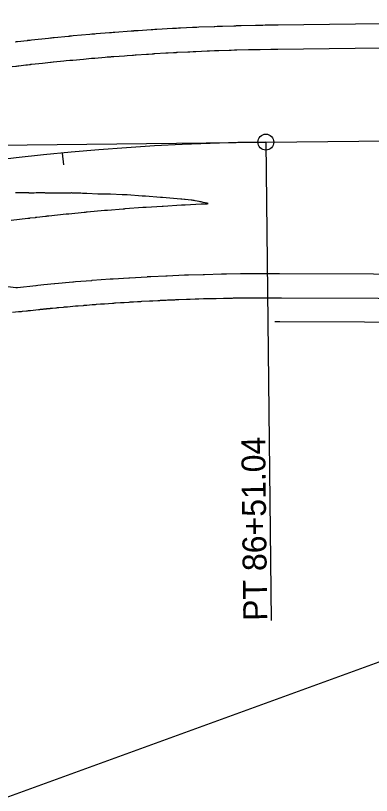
# Model space of a CAD drawing. Extents: x 1710723 to 1713003, y 548603 to 551142.
# Drawn here: x 1711329.1 to 1711418.2, y 549044.7 to 549240.3 of the extents above; entities that cross this region are included whole.
import ezdxf

# ---------------------------------------------------------------- set-up
doc = ezdxf.new("R2010")
doc.units = 0
for name, color, linetype in [('R_Contours', 7, 'Continuous'), ('R_Horz Alg', 7, 'Continuous'), ('R_Horz Alg Annot', 7, 'Continuous'), ('R_No Plot', 7, 'Continuous'), ('R_Striping', 7, 'Continuous')]:
    doc.layers.add(name, color=color, linetype=linetype)

msp = doc.modelspace()

# ---------------------------------------------------------------- linework, layer by layer
at = {"layer": 'R_Contours'}
for points in [[(1711581.85, 549240.26), (1711394.88, 549237.87), (1711394.67, 549237.87), (1711394.45, 549237.87), (1711394.24, 549237.86), (1711394.02, 549237.86), (1711391.64, 549237.82), (1711391.06, 549237.81), (1711390.38, 549237.8), (1711390.3, 549237.8), (1711390.21, 549237.8), (1711390.12, 549237.8), (1711390.03, 549237.79), (1711389.44, 549237.78), (1711389.31, 549237.78), (1711389.28, 549237.78), (1711389.25, 549237.78), (1711389.21, 549237.78), (1711389.18, 549237.78), (1711385.62, 549237.69), (1711385.15, 549237.68), (1711384.36, 549237.66), (1711384.2, 549237.65), (1711384.04, 549237.65), (1711383.88, 549237.64), (1711383.73, 549237.64), (1711380.94, 549237.55), (1711380.45, 549237.53), (1711379.9, 549237.51), (1711379.81, 549237.51), (1711379.73, 549237.51), (1711379.64, 549237.5), (1711379.55, 549237.5), (1711378.99, 549237.48), (1711378.89, 549237.48), (1711378.84, 549237.47), (1711378.79, 549237.47), (1711375.01, 549237.32), (1711374.46, 549237.29), (1711373.91, 549237.27), (1711373.77, 549237.26), (1711373.64, 549237.26), (1711373.5, 549237.25), (1711373.36, 549237.25), (1711370.35, 549237.1), (1711369.91, 549237.08), (1711369.41, 549237.05), (1711369.33, 549237.05), (1711369.25, 549237.04), (1711369.17, 549237.04), (1711369.09, 549237.03), (1711368.56, 549237.01), (1711368.46, 549237), (1711368.42, 549237), (1711368.4, 549237), (1711364.45, 549236.77), (1711363.97, 549236.74), (1711363.48, 549236.71), (1711363.36, 549236.71), (1711363.24, 549236.7), (1711363.12, 549236.69), (1711363, 549236.68), (1711359.78, 549236.47), (1711359.38, 549236.44), (1711358.94, 549236.42), (1711358.86, 549236.41), (1711358.79, 549236.41), (1711358.71, 549236.4), (1711358.63, 549236.39), (1711358.08, 549236.36), (1711358.03, 549236.35), (1711358.01, 549236.35), (1711353.97, 549236.05), (1711353.52, 549236.02), (1711353.08, 549235.98), (1711352.96, 549235.97), (1711352.85, 549235.97), (1711352.74, 549235.96), (1711352.63, 549235.95), (1711349.27, 549235.67), (1711348.89, 549235.64), (1711348.47, 549235.61), (1711348.4, 549235.6), (1711348.33, 549235.59), (1711348.26, 549235.59), (1711348.19, 549235.58), (1711347.69, 549235.54), (1711347.65, 549235.54), (1711347.64, 549235.53), (1711343.5, 549235.16), (1711343.09, 549235.12), (1711342.68, 549235.08), (1711342.58, 549235.07), (1711342.48, 549235.06), (1711342.38, 549235.05), (1711342.28, 549235.04), (1711338.76, 549234.7), (1711338.41, 549234.66), (1711338.02, 549234.62), (1711337.96, 549234.62), (1711337.89, 549234.61), (1711337.83, 549234.6), (1711337.77, 549234.6), (1711337.32, 549234.55), (1711337.28, 549234.55), (1711333.06, 549234.09), (1711332.68, 549234.05), (1711332.31, 549234.01), (1711332.22, 549234), (1711332.12, 549233.99), (1711332.03, 549233.98), (1711331.94, 549233.97), (1711329.56, 549233.7), (1711329.19, 549233.66), (1711329.14, 549233.65), (1711329.09, 549233.64), (1711329.03, 549233.64)], [(1711328.22, 549227.48), (1711329.11, 549227.6), (1711329.31, 549227.62), (1711329.64, 549227.66), (1711329.71, 549227.67), (1711329.77, 549227.68), (1711329.84, 549227.69), (1711329.91, 549227.7), (1711331.66, 549227.9), (1711332.03, 549227.94), (1711332.53, 549228), (1711332.66, 549228.01), (1711332.78, 549228.03), (1711332.91, 549228.04), (1711333.03, 549228.05), (1711335.79, 549228.35), (1711336.43, 549228.42), (1711337.81, 549228.57), (1711337.86, 549228.57), (1711337.91, 549228.58), (1711337.96, 549228.58), (1711338.01, 549228.59), (1711338.45, 549228.63), (1711338.5, 549228.64), (1711338.55, 549228.64), (1711341.18, 549228.9), (1711341.74, 549228.96), (1711342.67, 549229.05), (1711342.85, 549229.07), (1711343.04, 549229.09), (1711343.23, 549229.11), (1711343.41, 549229.12), (1711346.08, 549229.37), (1711346.71, 549229.42), (1711348.06, 549229.55), (1711348.12, 549229.55), (1711348.18, 549229.56), (1711348.23, 549229.56), (1711348.29, 549229.57), (1711348.68, 549229.6), (1711348.78, 549229.61), (1711348.84, 549229.61), (1711348.89, 549229.62), (1711351.5, 549229.83), (1711352.05, 549229.88), (1711352.95, 549229.95), (1711353.13, 549229.97), (1711353.32, 549229.98), (1711353.5, 549230), (1711353.68, 549230.01), (1711356.39, 549230.21), (1711357.01, 549230.26), (1711358.33, 549230.36), (1711358.39, 549230.36), (1711358.46, 549230.37), (1711358.52, 549230.37), (1711358.58, 549230.38), (1711359.02, 549230.41), (1711359.13, 549230.41), (1711359.19, 549230.42), (1711359.25, 549230.42), (1711361.84, 549230.59), (1711362.37, 549230.63), (1711363.25, 549230.69), (1711363.43, 549230.7), (1711363.6, 549230.71), (1711363.78, 549230.72), (1711363.96, 549230.73), (1711366.71, 549230.89), (1711367.32, 549230.92), (1711368.61, 549231), (1711368.68, 549231), (1711368.75, 549231.01), (1711368.82, 549231.01), (1711368.89, 549231.02), (1711369.37, 549231.04), (1711369.49, 549231.05), (1711369.53, 549231.05), (1711369.56, 549231.05), (1711369.59, 549231.05), (1711369.62, 549231.05), (1711372.21, 549231.18), (1711372.72, 549231.21), (1711373.56, 549231.25), (1711373.73, 549231.26), (1711373.9, 549231.26), (1711374.07, 549231.27), (1711374.24, 549231.28), (1711377.07, 549231.4), (1711377.66, 549231.42), (1711378.9, 549231.47), (1711378.98, 549231.48), (1711379.05, 549231.48), (1711379.13, 549231.48), (1711379.21, 549231.48), (1711379.73, 549231.5), (1711379.87, 549231.51), (1711379.9, 549231.51), (1711379.93, 549231.51), (1711379.97, 549231.51), (1711380, 549231.51), (1711382.59, 549231.6), (1711383.07, 549231.61), (1711383.88, 549231.64), (1711384.05, 549231.64), (1711384.21, 549231.65), (1711384.37, 549231.65), (1711384.53, 549231.66), (1711387.45, 549231.73), (1711388.03, 549231.75), (1711389.19, 549231.78), (1711389.28, 549231.78), (1711389.36, 549231.78), (1711389.45, 549231.78), (1711389.53, 549231.78), (1711390.11, 549231.79), (1711390.25, 549231.8), (1711390.28, 549231.8), (1711390.32, 549231.8), (1711390.35, 549231.8), (1711390.38, 549231.8), (1711393.01, 549231.84), (1711393.47, 549231.85), (1711394.22, 549231.86), (1711394.37, 549231.86), (1711394.52, 549231.87), (1711394.67, 549231.87), (1711394.82, 549231.87), (1711581.92, 549234.26)], [(1711327.96, 549188.93), (1711332.12, 549189.45), (1711332.17, 549189.45), (1711332.23, 549189.46), (1711332.59, 549189.5), (1711332.66, 549189.51), (1711332.72, 549189.52), (1711333.95, 549189.66), (1711334.06, 549189.67), (1711334.16, 549189.69), (1711334.26, 549189.7), (1711334.36, 549189.71), (1711336.58, 549189.96), (1711336.78, 549189.98), (1711336.98, 549190.01), (1711337.18, 549190.03), (1711337.38, 549190.05), (1711341.75, 549190.52), (1711341.8, 549190.52), (1711341.85, 549190.53), (1711342.26, 549190.57), (1711342.3, 549190.58), (1711342.35, 549190.58), (1711342.39, 549190.58), (1711342.44, 549190.59), (1711346.26, 549190.96), (1711346.44, 549190.98), (1711346.61, 549191), (1711346.79, 549191.02), (1711346.97, 549191.03), (1711351.32, 549191.43), (1711351.38, 549191.43), (1711351.44, 549191.44), (1711351.49, 549191.44), (1711351.55, 549191.45), (1711352.02, 549191.49), (1711352.06, 549191.49), (1711352.1, 549191.49), (1711356.02, 549191.81), (1711356.14, 549191.82), (1711356.26, 549191.83), (1711356.38, 549191.84), (1711356.5, 549191.85), (1711360.95, 549192.18), (1711361.02, 549192.18), (1711361.09, 549192.19), (1711361.16, 549192.19), (1711361.23, 549192.2), (1711361.75, 549192.24), (1711361.79, 549192.24), (1711361.81, 549192.24), (1711365.79, 549192.5), (1711365.86, 549192.5), (1711365.92, 549192.51), (1711365.99, 549192.51), (1711366.05, 549192.51), (1711370.67, 549192.78), (1711370.71, 549192.78), (1711370.75, 549192.78), (1711370.8, 549192.79), (1711370.84, 549192.79), (1711371.5, 549192.82), (1711371.52, 549192.83), (1711375.57, 549193.02), (1711375.6, 549193.02), (1711375.61, 549193.02), (1711377.06, 549193.08), (1711377.24, 549193.1), (1711377.3, 549193.12), (1711377.24, 549193.16), (1711377.07, 549193.2), (1711376.06, 549193.42), (1711375.81, 549193.47), (1711375.57, 549193.52), (1711375.32, 549193.58), (1711375.08, 549193.63), (1711374.09, 549193.83), (1711373.85, 549193.88), (1711373.6, 549193.92), (1711373.35, 549193.95), (1711373.1, 549193.98), (1711371.56, 549194.15), (1711371.55, 549194.15), (1711371.54, 549194.15), (1711371.53, 549194.15), (1711371.52, 549194.15), (1711371.44, 549194.15), (1711371.43, 549194.15), (1711371.42, 549194.15), (1711370.72, 549194.22), (1711370.7, 549194.22), (1711370.68, 549194.23), (1711370.66, 549194.23), (1711370.64, 549194.23), (1711370.56, 549194.23), (1711370.54, 549194.23), (1711370.52, 549194.23), (1711370.5, 549194.23), (1711370.48, 549194.23), (1711365.88, 549194.65), (1711365.84, 549194.65), (1711365.79, 549194.65), (1711365.75, 549194.65), (1711365.7, 549194.66), (1711365.52, 549194.66), (1711365.48, 549194.66), (1711365.43, 549194.66), (1711365.39, 549194.66), (1711365.35, 549194.67), (1711361.62, 549194.96), (1711361.6, 549194.96), (1711361.59, 549194.96), (1711361.58, 549194.96), (1711361.57, 549194.96), (1711361.53, 549194.97), (1711361.52, 549194.97), (1711361.51, 549194.97), (1711361.5, 549194.97), (1711361.48, 549194.97), (1711361.05, 549195), (1711360.97, 549195.01), (1711360.9, 549195.01), (1711360.82, 549195.02), (1711360.74, 549195.02), (1711357.06, 549195.28), (1711356.95, 549195.29), (1711356.85, 549195.29), (1711356.74, 549195.29), (1711356.63, 549195.3), (1711356.21, 549195.3), (1711356.1, 549195.3), (1711355.99, 549195.3), (1711355.89, 549195.3), (1711355.78, 549195.31), (1711352.85, 549195.48), (1711352.74, 549195.49), (1711352.63, 549195.49), (1711352.51, 549195.5), (1711352.4, 549195.5), (1711351.75, 549195.49), (1711351.7, 549195.49), (1711351.62, 549195.49), (1711351.6, 549195.49), (1711351.58, 549195.49), (1711351.56, 549195.49), (1711351.55, 549195.49), (1711351.21, 549195.51), (1711351.15, 549195.51), (1711351.09, 549195.51), (1711351.03, 549195.51), (1711350.96, 549195.51), (1711350.25, 549195.5), (1711350.11, 549195.5), (1711349.97, 549195.5), (1711349.83, 549195.51), (1711349.69, 549195.51), (1711346.94, 549195.63), (1711346.56, 549195.65), (1711346.18, 549195.67), (1711345.79, 549195.68), (1711345.41, 549195.7), (1711343.43, 549195.77), (1711343.27, 549195.77), (1711343.11, 549195.78), (1711342.95, 549195.78), (1711342.79, 549195.77), (1711341.87, 549195.75), (1711341.83, 549195.75), (1711341.78, 549195.75), (1711341.7, 549195.74), (1711341.68, 549195.74), (1711341.66, 549195.74), (1711341.63, 549195.74), (1711341.61, 549195.74), (1711341.36, 549195.75), (1711341.31, 549195.75), (1711341.26, 549195.75), (1711341.21, 549195.75), (1711341.16, 549195.75), (1711340.11, 549195.72), (1711339.91, 549195.71), (1711339.72, 549195.71), (1711339.53, 549195.71), (1711339.34, 549195.71), (1711336.81, 549195.77), (1711336.58, 549195.77), (1711336.35, 549195.78), (1711336.11, 549195.78), (1711335.88, 549195.79), (1711334.76, 549195.8), (1711334.63, 549195.81), (1711334.5, 549195.8), (1711334.37, 549195.8), (1711334.24, 549195.8), (1711333.7, 549195.77), (1711333.58, 549195.77), (1711333.46, 549195.77), (1711333.34, 549195.77), (1711333.22, 549195.77), (1711332.64, 549195.77), (1711332.57, 549195.77), (1711332.5, 549195.77), (1711332.43, 549195.77), (1711332.35, 549195.78), (1711331.96, 549195.78), (1711331.89, 549195.78), (1711331.75, 549195.78), (1711331.7, 549195.78), (1711331.68, 549195.78), (1711331.5, 549195.78), (1711331.46, 549195.78), (1711331.42, 549195.78), (1711331.38, 549195.78), (1711331.34, 549195.78), (1711329.04, 549195.79)], [(1711583.38, 549174.8), (1711395.23, 549175.51), (1711395.15, 549175.51), (1711395.08, 549175.51), (1711394.85, 549175.51), (1711394.77, 549175.51), (1711391.34, 549175.52), (1711391.31, 549175.52), (1711391.24, 549175.52), (1711390.54, 549175.52), (1711390.5, 549175.52), (1711390.46, 549175.52), (1711390.41, 549175.52), (1711390.37, 549175.52), (1711390.15, 549175.51), (1711390.02, 549175.51), (1711385.83, 549175.48), (1711385.8, 549175.48), (1711385.76, 549175.48), (1711385.73, 549175.48), (1711385.7, 549175.48), (1711385.49, 549175.48), (1711385.43, 549175.47), (1711381.88, 549175.42), (1711381.86, 549175.42), (1711381.8, 549175.42), (1711381.14, 549175.41), (1711381.11, 549175.41), (1711381.07, 549175.4), (1711381.03, 549175.4), (1711380.99, 549175.4), (1711380.77, 549175.4), (1711380.69, 549175.4), (1711376.43, 549175.29), (1711376.4, 549175.29), (1711376.37, 549175.29), (1711376.34, 549175.29), (1711376.32, 549175.29), (1711376.11, 549175.28), (1711376.08, 549175.28), (1711372.43, 549175.17), (1711372.36, 549175.16), (1711371.74, 549175.14), (1711371.71, 549175.14), (1711371.68, 549175.14), (1711371.65, 549175.14), (1711371.62, 549175.14), (1711371.42, 549175.13), (1711371.36, 549175.13), (1711367.04, 549174.95), (1711367.01, 549174.95), (1711366.99, 549174.95), (1711366.96, 549174.95), (1711366.94, 549174.95), (1711366.76, 549174.94), (1711366.74, 549174.94), (1711362.97, 549174.75), (1711362.93, 549174.75), (1711362.35, 549174.72), (1711362.29, 549174.72), (1711362.24, 549174.72), (1711362.06, 549174.71), (1711362.04, 549174.7), (1711357.64, 549174.45), (1711357.6, 549174.45), (1711357.56, 549174.45), (1711357.41, 549174.44), (1711353.52, 549174.19), (1711353.49, 549174.18), (1711352.95, 549174.15), (1711352.92, 549174.14), (1711352.88, 549174.14), (1711352.72, 549174.13), (1711348.26, 549173.8), (1711348.23, 549173.8), (1711348.2, 549173.8), (1711348.09, 549173.79), (1711344.08, 549173.46), (1711344.07, 549173.46), (1711343.57, 549173.42), (1711343.52, 549173.41), (1711343.42, 549173.4), (1711338.87, 549172.99), (1711338.85, 549172.99), (1711338.81, 549172.99), (1711336.12, 549172.73), (1711336.1, 549172.72), (1711334.65, 549172.58), (1711334.19, 549172.53), (1711334.14, 549172.53), (1711329.51, 549172.03), (1711329.51, 549172.03), (1711329.27, 549172), (1711329.23, 549172), (1711329.19, 549172), (1711329.15, 549172), (1711329.11, 549172), (1711325.12, 549172.52)], [(1711328.3, 549165.85), (1711329.77, 549166.02), (1711330.02, 549166.05), (1711330.27, 549166.08), (1711330.51, 549166.1), (1711330.76, 549166.13), (1711331.76, 549166.24), (1711332.01, 549166.26), (1711332.26, 549166.29), (1711332.51, 549166.32), (1711332.76, 549166.34), (1711334.84, 549166.57), (1711334.89, 549166.57), (1711334.94, 549166.58), (1711335.15, 549166.6), (1711335.32, 549166.62), (1711335.39, 549166.62), (1711335.42, 549166.63), (1711335.83, 549166.67), (1711335.99, 549166.68), (1711336.14, 549166.7), (1711336.6, 549166.74), (1711336.7, 549166.75), (1711336.8, 549166.76), (1711336.9, 549166.77), (1711337.01, 549166.78), (1711337.69, 549166.85), (1711337.84, 549166.86), (1711337.99, 549166.88), (1711338.14, 549166.89), (1711338.29, 549166.91), (1711339.14, 549166.99), (1711339.33, 549167.01), (1711339.52, 549167.03), (1711339.71, 549167.04), (1711339.9, 549167.06), (1711341.04, 549167.16), (1711341.29, 549167.19), (1711341.54, 549167.21), (1711341.8, 549167.23), (1711342.05, 549167.26), (1711344.09, 549167.44), (1711344.15, 549167.44), (1711344.21, 549167.45), (1711344.42, 549167.47), (1711344.61, 549167.48), (1711344.65, 549167.49), (1711344.68, 549167.49), (1711344.72, 549167.49), (1711344.76, 549167.5), (1711346.04, 549167.6), (1711346.27, 549167.62), (1711346.49, 549167.64), (1711346.72, 549167.66), (1711346.94, 549167.67), (1711348.28, 549167.78), (1711348.53, 549167.8), (1711348.79, 549167.82), (1711349.05, 549167.84), (1711349.3, 549167.86), (1711350.33, 549167.94), (1711350.58, 549167.96), (1711350.84, 549167.98), (1711351.1, 549167.99), (1711351.35, 549168.01), (1711353.36, 549168.16), (1711353.39, 549168.16), (1711353.43, 549168.17), (1711353.46, 549168.17), (1711353.49, 549168.17), (1711353.69, 549168.18), (1711353.94, 549168.2), (1711353.98, 549168.2), (1711354.02, 549168.21), (1711354.06, 549168.21), (1711354.11, 549168.21), (1711355.38, 549168.29), (1711355.6, 549168.31), (1711355.83, 549168.32), (1711356.05, 549168.34), (1711356.28, 549168.35), (1711357.55, 549168.43), (1711357.81, 549168.45), (1711358.07, 549168.47), (1711358.33, 549168.48), (1711358.59, 549168.5), (1711359.63, 549168.56), (1711359.89, 549168.57), (1711360.15, 549168.59), (1711360.41, 549168.6), (1711360.67, 549168.62), (1711362.63, 549168.73), (1711362.67, 549168.73), (1711362.71, 549168.73), (1711362.75, 549168.73), (1711362.78, 549168.74), (1711363.01, 549168.75), (1711363.08, 549168.75), (1711363.28, 549168.76), (1711363.32, 549168.76), (1711363.37, 549168.77), (1711363.41, 549168.77), (1711363.46, 549168.77), (1711364.72, 549168.83), (1711364.94, 549168.84), (1711365.17, 549168.85), (1711365.39, 549168.86), (1711365.62, 549168.88), (1711366.82, 549168.93), (1711367.09, 549168.95), (1711367.35, 549168.96), (1711367.61, 549168.97), (1711367.88, 549168.98), (1711368.93, 549169.02), (1711369.19, 549169.03), (1711369.46, 549169.04), (1711369.72, 549169.06), (1711369.98, 549169.07), (1711371.91, 549169.14), (1711371.95, 549169.15), (1711371.99, 549169.15), (1711372.04, 549169.15), (1711372.08, 549169.15), (1711372.29, 549169.16), (1711372.41, 549169.16), (1711372.62, 549169.17), (1711372.67, 549169.17), (1711372.72, 549169.17), (1711372.77, 549169.17), (1711372.82, 549169.18), (1711374.06, 549169.22), (1711374.29, 549169.22), (1711374.51, 549169.23), (1711374.74, 549169.24), (1711374.96, 549169.24), (1711376.11, 549169.28), (1711376.37, 549169.29), (1711376.64, 549169.3), (1711376.9, 549169.3), (1711377.17, 549169.31), (1711378.24, 549169.34), (1711378.5, 549169.34), (1711378.77, 549169.35), (1711379.04, 549169.35), (1711379.3, 549169.36), (1711381.19, 549169.41), (1711381.24, 549169.41), (1711381.28, 549169.41), (1711381.33, 549169.41), (1711381.38, 549169.41), (1711381.61, 549169.41), (1711381.74, 549169.42), (1711381.97, 549169.42), (1711382.02, 549169.42), (1711382.08, 549169.42), (1711382.13, 549169.42), (1711382.18, 549169.43), (1711383.41, 549169.44), (1711383.64, 549169.45), (1711383.86, 549169.45), (1711384.08, 549169.45), (1711384.3, 549169.46), (1711385.41, 549169.47), (1711385.67, 549169.48), (1711385.93, 549169.48), (1711386.19, 549169.48), (1711386.45, 549169.49), (1711387.54, 549169.49), (1711387.81, 549169.5), (1711388.08, 549169.5), (1711388.35, 549169.5), (1711388.62, 549169.5), (1711390.47, 549169.52), (1711390.52, 549169.52), (1711390.57, 549169.52), (1711390.62, 549169.52), (1711390.67, 549169.52), (1711390.92, 549169.52), (1711391.07, 549169.52), (1711391.32, 549169.52), (1711391.37, 549169.52), (1711391.43, 549169.52), (1711391.49, 549169.52), (1711391.55, 549169.52), (1711392.75, 549169.52), (1711392.97, 549169.52), (1711393.19, 549169.52), (1711393.41, 549169.52), (1711393.63, 549169.52), (1711394.71, 549169.51), (1711394.97, 549169.51), (1711395.22, 549169.51), (1711395.47, 549169.51), (1711395.73, 549169.51), (1711565.01, 549168.87)], [(1711393.99, 549163.52), (1711395.29, 549163.51), (1711395.3, 549163.51), (1711564.99, 549162.87)]]:
    msp.add_lwpolyline(points, dxfattribs=at)
at = {"layer": 'R_Horz Alg'}
msp.add_line((1711391.77, 549208.53), (1711733, 549212.35), dxfattribs=at)
msp.add_arc((1711398.54, 548605.45), 603.11, 90.64281, 132.74131, dxfattribs=at)
at = {"layer": 'R_Horz Alg Annot'}
msp.add_line((1711159.68, 549205.92), (1711391.77, 549208.53), dxfattribs=at)
for points in [[(1711391.77, 549208.53), (1711393.12, 549088.53)], [(1711341.11, 549202.81), (1711340.82, 549205.8)]]:
    msp.add_lwpolyline(points, dxfattribs=at)
msp.add_circle((1711391.77, 549208.53), 2, dxfattribs=at)
at = {"layer": 'R_No Plot'}
msp.add_line((1711663.44, 549166.72), (1711305.56, 549036.46), dxfattribs=at)
at = {"layer": 'R_Striping'}
msp.add_line((1711391.77, 549208.53), (1711733, 549212.35), dxfattribs=at)
msp.add_arc((1711398.54, 548605.45), 603.11, 90.64281, 132.74131, dxfattribs=at)

# ---------------------------------------------------------------- texts
at = {"layer": 'R_Horz Alg Annot'}
msp.add_text('PT 86+51.04', height=6, rotation=90.6428, dxfattribs=at).set_placement((1711392.12, 549088.52))

doc.saveas('drawing.dxf')
